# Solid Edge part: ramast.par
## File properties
Username: Kasutaja
Author: Kasutaja
Template: Iso Metric Part.par
Last saved by: Kasutaja
Revision: 7
Application: Solid Edge
Accuracy: 0,990
Face Style: Model Default
Fill Style: Normal
Coef. of Thermal Exp: 0.0
Thermal Conductivity: 0.0
Specific Heat: 0.0
Modulus of Elasticity: 0.0
Poisson's Ratio: 0.0
Yield Stress: 0.0
Ultimate Stress: 0.0
Elongation: 0.0
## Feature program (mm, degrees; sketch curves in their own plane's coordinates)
sketch for "unnamed Protrusion 1" plane through (0, 0, 0) normal (0, 0, 1) x-axis (1, 0, 0)
  circle centre (0, 0) radius 6
extrude "unnamed Protrusion 1" add finite 470 along +normal
fillet "Round_1" radius 5
sketch for "ExtrudedProtrusion_2" plane through (0, 0, 0) normal (1, 0, 0) x-axis (0, 1, 0)
  circle centre (-4.329, 380) radius 5.8704
extrude "ExtrudedProtrusion_2" add finite 450 symmetric
fillet "Round_2" radius 2
sketch for "ExtrudedCutout_1" plane through (0, 0, 0) normal (1, 0, 0) x-axis (0, 1, 0)
  circle centre (-4.329, 380) radius 6.1135
extrude "ExtrudedCutout_1" cut finite 12 symmetric
sketch for "ExtrudedProtrusion_5" plane through (0, 0, 0) normal (1, 0, 0) x-axis (0, 1, 0)
  circle centre (-4.329, 380) radius 5.8704
extrude "ExtrudedProtrusion_5" add finite 18.9642 symmetric
sketch for "ExtrudedCutout_2" plane through (0, 0, 0) normal (0, 0, -1) x-axis (0, 1, 0)
  circle centre (0.0209, 0) radius 2.5
extrude "ExtrudedCutout_2" cut finite 0.01 symmetric
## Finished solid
Body 1: solid body, 12 faces, 10 edges, 0 vertices, 2 separate solids.
  Faces by surface: plane 5, cylinder 4, torus 3
  Edges by curve: circle 9, intersection 1
Bounding box of the edges (mm; curved faces can reach further): 450.000 x 16.199 x 470.000, from (-225, -10.1994, 0) to (225, 6, 470).
Cylindrical faces by radius (mm): R2.5 x1, R5.8704 x1, R6 x1, R6.1135 x1
Toroidal faces (ring radius, tube radius in mm): R1 r5 x1, R3.8704 r2 x2
Planar faces by outward normal: +x 1, +z 1, -x 1, -z 2
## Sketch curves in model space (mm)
circle centre (0, 0.0209, 0) radius 2.5
circle centre (0, -4.329, 380) radius 6.1135
circle centre (0, -4.329, 380) radius 5.8704
circle centre (0, 0, 0) radius 6
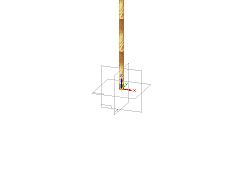
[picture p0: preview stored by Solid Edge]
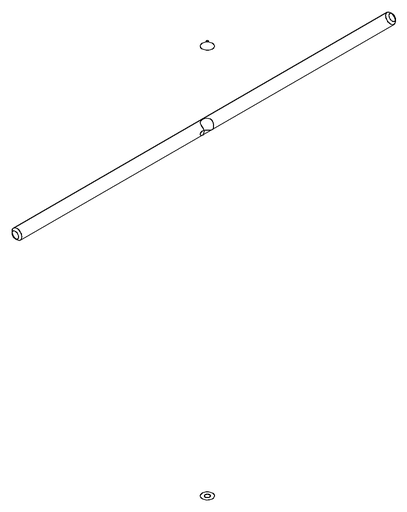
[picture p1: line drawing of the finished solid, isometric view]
